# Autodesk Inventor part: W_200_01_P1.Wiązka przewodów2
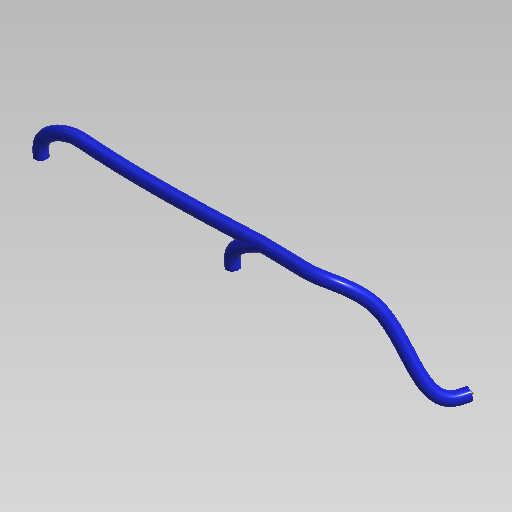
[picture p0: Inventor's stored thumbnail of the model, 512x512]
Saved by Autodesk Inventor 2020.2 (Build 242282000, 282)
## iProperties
Manager: www.cadconsulting.pl
Company: Fabian Stasiak CAD Consulting
Created: 2014-09
Part Number: W_200_01_P1.Wiązka przewodów2
Material: Ogólne
Document SubType Name: Modelowanie
Designer: F.Stasiak
Appearance: Ogólne
Catalog Web Link: www.expertbooks.pl
Author: F.Stasiak
Subject: Zbiór ćwiczeń. Autodesk Inventor 2020. Kurs Professional
## Parameters: d2 = 0, d3 = 0, d4 = 0, d5 = 0, d6 = 0, d7 = 0
